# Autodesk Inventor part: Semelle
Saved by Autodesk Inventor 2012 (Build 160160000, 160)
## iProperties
Created: 2013-08
Part Number: Semelle
Material: Default
Document SubType Name: Modeling
Designer: hilarion
Density: 1 g/cm^3
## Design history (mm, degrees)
node "Semelle1"
node "Semelle"
node "Base1"
